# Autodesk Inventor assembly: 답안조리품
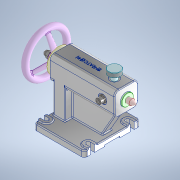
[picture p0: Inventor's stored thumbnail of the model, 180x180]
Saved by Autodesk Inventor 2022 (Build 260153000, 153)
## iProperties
Created: 2024-07
Part Number: 답안조리품
Document SubType Name: Assembly
Designer: PC-01
Author: PC-01
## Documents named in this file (15)
- C:\Users\PC-01\Downloads\740704V1006\답안조리품.iam
- C:\Users\PC-01\Downloads\740704V1006\본체.ipt
- C:\Users\PC-01\Downloads\740704V1006\부시.ipt
- C:\Users\PC-01\Downloads\740704V1006\스러스트 볼 베어링 51101.ipt
- C:\Users\PC-01\Downloads\740704V1006\나사축.ipt
- C:\Users\PC-01\Downloads\740704V1006\평행키 4x4x14.ipt
- C:\Users\PC-01\Downloads\740704V1006\핸들.ipt
- C:\Users\PC-01\Downloads\740704V1006\평와셔 M12.ipt
- C:\Users\PC-01\Downloads\740704V1006\스프링  와셔 M12.ipt
- C:\Users\PC-01\Downloads\740704V1006\캡너트 M12.ipt
- C:\Users\PC-01\Downloads\740704V1006\슬리브.ipt
- C:\Users\PC-01\Downloads\740704V1006\육각 소켓 머리 볼트 M6x12.ipt
- C:\Users\PC-01\Downloads\740704V1006\스톱퍼.ipt
- C:\Users\PC-01\Downloads\740704V1006\센터.ipt
- C:\Users\PC-01\Downloads\740704V1006\육각 소켓 머리 볼트 M12x16.ipt
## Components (1 placed, 1 different names)
1. 핸들:1
